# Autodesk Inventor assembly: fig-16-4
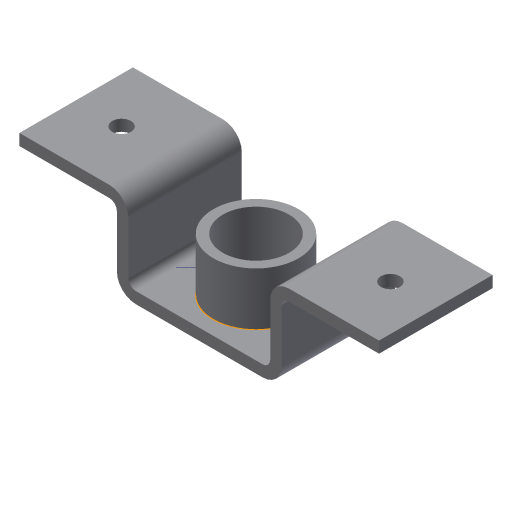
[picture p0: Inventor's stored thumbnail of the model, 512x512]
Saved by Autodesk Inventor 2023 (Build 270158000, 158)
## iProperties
Created: 2004-07
Part Number: fig-16-4
Document SubType Name: Weldment
Designer: CADCIM Technologies
Manufacturer: Standard
Standards Organization: Custom
Author: CADCIM Technologies
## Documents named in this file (3)
- D:\PROJECTS\Project 2022\Autodesk Inventor For Professional 2023\RESOURCES INVENTOR 2023\RESOURCES INVENTOR 2023\Inventor_2023_Part\Inventor_2023_Part\c16_Inv_2023_prt\fig-16-4.iam
- D:\PROJECTS\Project 2022\Autodesk Inventor For Professional 2023\RESOURCES INVENTOR 2023\RESOURCES INVENTOR 2023\Inventor_2023_Part\Inventor_2023_Part\c16_Inv_2023_prt\Bracket.ipt
- D:\PROJECTS\Project 2022\Autodesk Inventor For Professional 2023\RESOURCES INVENTOR 2023\RESOURCES INVENTOR 2023\Inventor_2023_Part\Inventor_2023_Part\c16_Inv_2023_prt\cylinder.ipt
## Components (2 placed, 2 different names)
1. Bracket:1 — Insert:1
2. cylinder:1 — Insert:1
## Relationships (1: Insert 1)
- Insert:1: Bracket:1 ↔ cylinder:1
